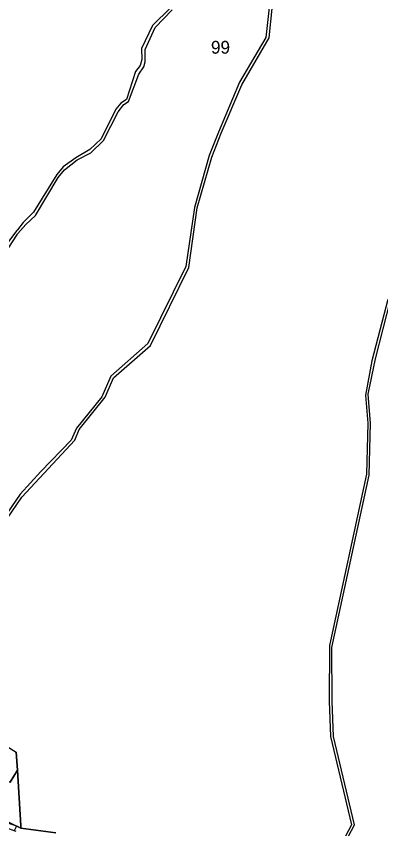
# Model space of a CAD drawing. Extents: x -477304 to -465429, y -1159113 to -1149210.
# Drawn here: x -474566 to -474140, y -1157226 to -1156274 of the extents above; entities that cross this region are included whole.
import ezdxf

# ---------------------------------------------------------------- set-up
doc = ezdxf.new("R2010")
doc.units = 0
doc.layers.add('BPEJ_s', color=7, linetype='Continuous')
doc.layers.add('PUPFL_s', color=7, linetype='Continuous')

msp = doc.modelspace()

# ---------------------------------------------------------------- linework, layer by layer
at = {"layer": 'BPEJ_s'}
for points in [[(-474582.45, -1157123.89), (-474586.17, -1157130.66), (-474584.16, -1157130.41), (-474605.49, -1157169.45), (-474607.69, -1157169.78), (-474612.24, -1157178.05), (-474609.75, -1157177.25), (-474612.17, -1157181.44), (-474603.51, -1157191.69), (-474595.49, -1157202.12), (-474593.88, -1157213.76), (-474568.54, -1157221.72), (-474565.8, -1157222.58), (-474565.99, -1157222.94), (-474568.82, -1157228.32)], [(-474568.54, -1157221.72), (-474565.8, -1157222.58), (-474565.99, -1157222.94), (-474568.82, -1157228.32)]]:
    msp.add_lwpolyline(points, dxfattribs=at)
at = {"layer": 'PUPFL_s'}
for points in [[(-474266.23, -1156228.06), (-474274.31, -1156298.93), (-474305.03, -1156351.35), (-474329.68, -1156409.83), (-474340.53, -1156437.13), (-474357.49, -1156498.25), (-474367.86, -1156567.04), (-474412.39, -1156657.59), (-474455.69, -1156695.82), (-474466.29, -1156719.93), (-474495.75, -1156756.75), (-474502.08, -1156770.87), (-474537.48, -1156807.58), (-474561.74, -1156834.07), (-474576.86, -1156856.4)], [(-474589.27, -1156880.49), (-474559.69, -1156837.53), (-474497.57, -1156770.53), (-474492.69, -1156758.36), (-474462.31, -1156720.2), (-474452.37, -1156697.82), (-474409.28, -1156659.83), (-474364.44, -1156568.58), (-474354.48, -1156498.35), (-474337.52, -1156438.97), (-474326.25, -1156411.03), (-474302.2, -1156354.36), (-474270.29, -1156299.09), (-474263.12, -1156230.32)], [(-474385.73, -1156264.08), (-474406.97, -1156284.69), (-474419.58, -1156311.59), (-474419.21, -1156324.6), (-474421.32, -1156331.6), (-474426.65, -1156338.91), (-474437.3, -1156371.69), (-474444, -1156375.82), (-474449.63, -1156382.69), (-474467.05, -1156417.59), (-474480.27, -1156430.32), (-474496.66, -1156439.78), (-474511.4, -1156450.38), (-474518.69, -1156459.48), (-474546.18, -1156503.75), (-474558.05, -1156515.85), (-474564.96, -1156524.1), (-474565.62, -1156524.98), (-474577.69, -1156541.04)], [(-474575.68, -1156545.96), (-474564.93, -1156529.28), (-474564.35, -1156528.39), (-474554.94, -1156518.06), (-474543.6, -1156507.27), (-474517.45, -1156462.84), (-474509.65, -1156453.76), (-474495.11, -1156442.43), (-474479.2, -1156434.11), (-474464.27, -1156419.63), (-474447.15, -1156386.11), (-474440.38, -1156377.59), (-474434.72, -1156373.77), (-474422.96, -1156341.76), (-474416.79, -1156333.31), (-474415.49, -1156327.24), (-474415.55, -1156312.94), (-474403.52, -1156287.08), (-474383.82, -1156266.63)], [(-474131.17, -1156605.89), (-474149.87, -1156677.69), (-474157.51, -1156717.86), (-474154.56, -1156750.68), (-474156.43, -1156810.69), (-474199.69, -1157011.23), (-474199.94, -1157076.73), (-474198.35, -1157118.08), (-474173.99, -1157221.42), (-474191.12, -1157254)], [(-474134.86, -1157559.49), (-474148.49, -1157510.37), (-474156.14, -1157482.43), (-474153.3, -1157479.65), (-474150.45, -1157461.21), (-474175.73, -1157346.37), (-474181.07, -1157313.94), (-474187.44, -1157253.89), (-474170.29, -1157221.53), (-474194.97, -1157118.03), (-474196.27, -1157076.48), (-474196.74, -1157013.81), (-474153.29, -1156811.71), (-474151.41, -1156750.96), (-474154.39, -1156716.69), (-474145.88, -1156675.24), (-474127.91, -1156605.09)], [(-474520.06, -1157230.66), (-474560.83, -1157225.42), (-474561, -1157222.59), (-474564.87, -1157157.45), (-474566.57, -1157136.41)], [(-474566.5, -1157229.14), (-474596.12, -1157218.7), (-474598.76, -1157225.82), (-474606.02, -1157217.85), (-474629.62, -1157222.07), (-474631.77, -1157222.45), (-474632, -1157222.05), (-474633.21, -1157219.92), (-474596.58, -1157208.26), (-474572.19, -1157219.97), (-474560.83, -1157225.42), (-474520.06, -1157230.66)]]:
    msp.add_lwpolyline(points, dxfattribs=at)
for points in [[(-474584.16, -1157130.41), (-474577.01, -1157129.52), (-474566.57, -1157136.41), (-474564.87, -1157157.45), (-474573.26, -1157171.3), (-474594.56, -1157167.78), (-474605.49, -1157169.45)], [(-474560.83, -1157225.42), (-474572.19, -1157219.97), (-474596.58, -1157208.26), (-474615.85, -1157187.83), (-474609.75, -1157177.25), (-474605.49, -1157169.45), (-474594.56, -1157167.78), (-474573.26, -1157171.3), (-474564.87, -1157157.45), (-474561, -1157222.59)]]:
    msp.add_lwpolyline(points, close=True, dxfattribs=at)

# ---------------------------------------------------------------- texts
at = {"layer": 'BPEJ_s'}
msp.add_text('99', height=15, dxfattribs=at).set_placement((-474338.36, -1156317.88))

doc.saveas('drawing.dxf')
